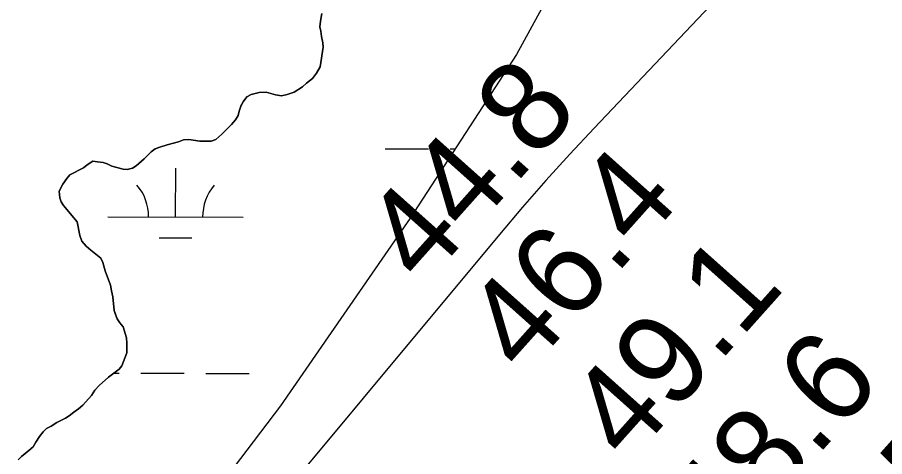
# Model space of a CAD drawing. Extents: x 3172297 to 3210190, y 958463 to 983887.
# Drawn here: x 3193154 to 3193795, y 965148 to 965472 of the extents above; entities that cross this region are included whole.
import ezdxf

# ---------------------------------------------------------------- set-up
doc = ezdxf.new("R2010")
doc.units = 0
for name, color, linetype in [('V-RIVR-RANG', 7, 'Continuous'), ('V-SITE-VEGE', 7, 'Continuous'), ('V-TOPO-MINR', 7, 'Continuous'), ('V-TOPO-SHOR', 7, 'Continuous'), ('V-WETL-SWMP', 7, 'Continuous')]:
    doc.layers.add(name, color=color, linetype=linetype)

msp = doc.modelspace()

# ---------------------------------------------------------------- linework, layer by layer
at = {"layer": 'V-SITE-VEGE'}
for p, q in [((3193379.05, 965474.97), (3193378.03, 965469.46)), ((3193378.03, 965469.46), (3193377.7, 965465.32)), ((3193377.7, 965465.32), (3193378.4, 965461.88)), ((3193378.4, 965461.88), (3193378.76, 965458.09)), ((3193378.76, 965458.09), (3193379.81, 965453.27)), ((3193380.16, 965450.18), (3193377.8, 965435.7)), ((3193379.81, 965453.27), (3193380.16, 965450.18)), ((3193377.8, 965435.7), (3193375.06, 965430.87)), ((3193375.06, 965430.87), (3193372.31, 965427.07)), ((3193367.85, 965423.61), (3193364.76, 965420.85)), ((3193372.31, 965427.07), (3193367.85, 965423.61)), ((3193332.74, 965416.61), (3193326.89, 965415.21)), ((3193337.9, 965416.97), (3193332.74, 965416.61)), ((3193344.8, 965414.93), (3193337.9, 965416.97)), ((3193358.57, 965417.04), (3193353.41, 965415.3)), ((3193364.76, 965420.85), (3193358.57, 965417.04)), ((3193321.05, 965409.69), (3193319.34, 965406.58)), ((3193323.79, 965413.48), (3193321.05, 965409.69)), ((3193326.89, 965415.21), (3193323.79, 965413.48)), ((3193349.28, 965414.25), (3193344.8, 965414.93)), ((3193353.41, 965415.3), (3193349.28, 965414.25)), ((3193319.34, 965406.58), (3193317.97, 965402.79)), ((3193315.24, 965396.58), (3193312.49, 965393.12)), ((3193317.29, 965399.68), (3193315.24, 965396.58)), ((3193317.97, 965402.79), (3193317.29, 965399.68)), ((3193312.49, 965393.12), (3193305.28, 965385.87)), ((3193305.28, 965385.87), (3193300.82, 965382.06)), ((3193265.01, 965378.16), (3193259.5, 965376.42)), ((3193273.27, 965380.25), (3193265.01, 965378.16)), ((3193277.05, 965381.64), (3193273.27, 965380.25)), ((3193280.84, 965382), (3193277.05, 965381.64)), ((3193289.11, 965380.65), (3193280.84, 965382)), ((3193297.38, 965380.67), (3193289.11, 965380.65)), ((3193300.82, 965382.06), (3193297.38, 965380.67)), ((3193252.97, 965372.95), (3193247.82, 965367.77)), ((3193256.06, 965375.03), (3193252.97, 965372.95)), ((3193259.5, 965376.42), (3193256.06, 965375.03)), ((3193209.94, 965365.92), (3193205.81, 965363.15)), ((3193213.38, 965365.59), (3193209.94, 965365.92)), ((3193217.52, 965364.91), (3193213.38, 965365.59)), ((3193220.62, 965363.89), (3193217.52, 965364.91)), ((3193247.82, 965367.77), (3193241.98, 965362.58)), ((3193203.06, 965361.08), (3193193.09, 965355.88)), ((3193205.81, 965363.15), (3193203.06, 965361.08)), ((3193224.07, 965362.18), (3193220.62, 965363.89)), ((3193232.34, 965360.14), (3193224.07, 965362.18)), ((3193235.45, 965359.81), (3193232.34, 965360.14)), ((3193239.23, 965360.85), (3193235.45, 965359.81)), ((3193241.98, 965362.58), (3193239.23, 965360.85)), ((3193190.69, 965353.11), (3193187.95, 965348.97)), ((3193193.09, 965355.88), (3193190.69, 965353.11)), ((3193187.95, 965348.97), (3193185.21, 965343.8)), ((3193185.21, 965343.8), (3193185.57, 965338.98)), ((3193185.57, 965338.98), (3193186.61, 965335.88)), ((3193186.61, 965335.88), (3193188.35, 965333.13)), ((3193188.35, 965333.13), (3193198.37, 965321.11)), ((3193198.37, 965321.11), (3193200.47, 965311.13)), ((3193200.47, 965311.13), (3193201.86, 965306.99)), ((3193201.86, 965306.99), (3193204.98, 965303.22)), ((3193204.98, 965303.22), (3193208.43, 965300.13)), ((3193208.43, 965300.13), (3193216.03, 965294.3)), ((3193216.03, 965294.3), (3193217.41, 965291.2)), ((3193217.41, 965291.2), (3193219.16, 965285.01)), ((3193219.16, 965285.01), (3193222.98, 965274.34)), ((3193222.98, 965274.34), (3193223.68, 965270.21)), ((3193223.68, 965270.21), (3193224.73, 965265.74)), ((3193224.73, 965265.74), (3193225.79, 965255.75)), ((3193225.79, 965255.75), (3193227.88, 965249.56)), ((3193227.88, 965249.56), (3193229.96, 965246.46)), ((3193229.96, 965246.46), (3193232.38, 965243.72)), ((3193232.38, 965243.72), (3193234.82, 965235.46)), ((3193234.82, 965235.46), (3193235.17, 965231.67)), ((3193235.17, 965231.67), (3193235.2, 965224.44)), ((3193235.2, 965224.44), (3193231.44, 965214.78)), ((3193229.38, 965212.36), (3193221.48, 965206.48)), ((3193231.44, 965214.78), (3193229.38, 965212.36)), ((3193221.48, 965206.48), (3193214.61, 965200.26)), ((3193214.61, 965200.26), (3193211.52, 965196.81)), ((3193209.12, 965193.01), (3193202.6, 965185.76)), ((3193211.52, 965196.81), (3193209.12, 965193.01)), ((3193202.6, 965185.76), (3193199.51, 965182.99)), ((3193196.08, 965180.57), (3193192.64, 965177.8)), ((3193199.51, 965182.99), (3193196.08, 965180.57)), ((3193183.35, 965172.95), (3193179.23, 965170.18)), ((3193189.89, 965176.07), (3193183.35, 965172.95)), ((3193192.64, 965177.8), (3193189.89, 965176.07)), ((3193173.39, 965166.03), (3193170.64, 965162.57)), ((3193175.79, 965168.45), (3193173.39, 965166.03)), ((3193179.23, 965170.18), (3193175.79, 965168.45)), ((3193170.64, 965162.57), (3193167.9, 965158.43)), ((3193165.85, 965154.98), (3193162.75, 965152.21)), ((3193167.9, 965158.43), (3193165.85, 965154.98)), ((3193162.75, 965152.21), (3193157.26, 965147.72))]:
    msp.add_line(p, q, dxfattribs=at)
at = {"layer": 'V-TOPO-MINR'}
msp.add_lwpolyline([(3194372.18, 966226.17), (3193580.04, 965390.46), (3193562.15, 965371.22), (3193544.51, 965351.76), (3193527.25, 965331.96), (3193510.25, 965311.93), (3193009.1, 964710.23), (3193002.17, 964701.92), (3192995.24, 964693.61), (3192988.3, 964685.31), (3192981.36, 964677.01), (3192969.12, 964662.37), (3192968.29, 964661.4), (3192967.46, 964660.43), (3192965.75, 964658.52), (3192960.13, 964652.39), (3192956.44, 964648.39), (3192952.71, 964644.43), (3192948.94, 964640.51), (3192945.15, 964636.61), (3192809.87, 964499.28), (3192738.63, 964426.54), (3192667.68, 964353.51), (3192597.16, 964280.07)], dxfattribs=at)
at = {"layer": 'V-TOPO-SHOR'}
msp.add_lwpolyline([(3193154.85, 965145.3), (3193157.26, 965147.72), (3193162.75, 965152.21), (3193165.85, 965154.98), (3193167.9, 965158.43), (3193170.64, 965162.57), (3193173.39, 965166.03), (3193175.79, 965168.45), (3193179.23, 965170.18), (3193183.35, 965172.95), (3193189.89, 965176.07), (3193192.64, 965177.8), (3193196.07, 965180.57), (3193199.51, 965182.99), (3193202.6, 965185.76), (3193209.12, 965193.01), (3193211.52, 965196.81), (3193214.61, 965200.26), (3193221.48, 965206.48), (3193229.38, 965212.36), (3193231.44, 965214.78), (3193235.2, 965224.44), (3193235.17, 965231.67), (3193234.82, 965235.46), (3193232.38, 965243.72), (3193229.96, 965246.46), (3193227.88, 965249.56), (3193226.84, 965252.66), (3193225.79, 965255.75), (3193224.73, 965265.74), (3193223.68, 965270.21), (3193222.98, 965274.34), (3193219.16, 965285.01), (3193217.41, 965291.2), (3193216.03, 965294.3), (3193208.43, 965300.13), (3193204.98, 965303.22), (3193201.86, 965307), (3193200.47, 965311.13), (3193198.37, 965321.11), (3193188.35, 965333.13), (3193186.61, 965335.88), (3193185.57, 965338.98), (3193185.21, 965343.8), (3193187.95, 965348.97), (3193190.69, 965353.11), (3193193.09, 965355.88), (3193203.06, 965361.08), (3193205.81, 965363.15), (3193209.94, 965365.92), (3193213.38, 965365.59), (3193217.52, 965364.91), (3193220.62, 965363.89), (3193224.07, 965362.18), (3193232.34, 965360.14), (3193235.45, 965359.81), (3193239.23, 965360.85), (3193241.98, 965362.58), (3193247.82, 965367.77), (3193252.97, 965372.95), (3193256.06, 965375.03), (3193259.5, 965376.42), (3193265.01, 965378.16), (3193273.27, 965380.25), (3193277.05, 965381.64), (3193280.84, 965382), (3193289.11, 965380.65), (3193297.38, 965380.67), (3193300.82, 965382.06), (3193305.28, 965385.87), (3193312.49, 965393.12), (3193315.24, 965396.58), (3193317.29, 965399.68), (3193317.97, 965402.79), (3193319.34, 965406.58), (3193321.05, 965409.69), (3193323.79, 965413.48), (3193326.89, 965415.21), (3193332.74, 965416.61), (3193337.9, 965416.97), (3193344.8, 965414.93), (3193349.28, 965414.25), (3193353.41, 965415.3), (3193358.57, 965417.04), (3193364.76, 965420.85), (3193367.85, 965423.61), (3193372.31, 965427.07), (3193375.06, 965430.87), (3193377.8, 965435.7), (3193380.16, 965450.18), (3193379.81, 965453.27), (3193378.76, 965458.09), (3193378.4, 965461.88), (3193377.7, 965465.32), (3193378.03, 965469.46), (3193379.05, 965474.97)], dxfattribs=at)
at = {"layer": 'V-WETL-SWMP'}
for p, q in [((3193425.81, 965375.1), (3193457.81, 965375.02)), ((3193473.81, 965374.98), (3193477.46, 965374.97)), ((3193271.09, 965324.74), (3193271.18, 965360.74)), ((3193221.09, 965324.86), (3193321.09, 965324.62)), ((3193259.05, 965309.34), (3193283.05, 965309.28)), ((3193225.42, 965209.42), (3193229.4, 965209.41)), ((3193245.4, 965209.37), (3193277.4, 965209.29)), ((3193293.4, 965209.25), (3193325.4, 965209.17))]:
    msp.add_line(p, q, dxfattribs=at)
for points in [[(3193738.09, 965817.65), (3193624.49, 965630.72), (3193522.75, 965444.79), (3193444.26, 965323.8), (3193348.56, 965185.35), (3193249.16, 965054.18), (3193135.29, 964906.47), (3193014.29, 964734.08), (3193007.95, 964728.57), (3192766.54, 964428.5), (3192623.52, 964274.2)], [(3193154.85, 965145.3), (3193157.26, 965147.72), (3193162.75, 965152.21), (3193165.85, 965154.98), (3193167.9, 965158.43), (3193170.64, 965162.57), (3193173.39, 965166.03), (3193175.79, 965168.45), (3193179.23, 965170.18), (3193183.35, 965172.95), (3193189.89, 965176.07), (3193192.64, 965177.8), (3193196.07, 965180.57), (3193199.51, 965182.99), (3193202.6, 965185.76), (3193209.12, 965193.01), (3193211.52, 965196.81), (3193214.61, 965200.26), (3193221.48, 965206.48), (3193229.38, 965212.36), (3193231.44, 965214.78), (3193235.2, 965224.44), (3193235.17, 965231.67), (3193234.82, 965235.46), (3193232.38, 965243.72), (3193229.96, 965246.47), (3193227.88, 965249.56), (3193226.84, 965252.66), (3193225.79, 965255.75), (3193224.73, 965265.74), (3193223.68, 965270.21), (3193222.98, 965274.34), (3193219.16, 965285.01), (3193217.41, 965291.2), (3193216.02, 965294.3), (3193208.43, 965300.13), (3193204.97, 965303.22), (3193201.86, 965307), (3193200.47, 965311.13), (3193198.37, 965321.11), (3193188.34, 965333.13), (3193186.61, 965335.88), (3193185.57, 965338.98), (3193185.21, 965343.8), (3193187.95, 965348.97), (3193190.69, 965353.12), (3193193.09, 965355.88), (3193203.06, 965361.08), (3193205.81, 965363.15), (3193209.94, 965365.92), (3193213.38, 965365.59), (3193217.52, 965364.91), (3193220.62, 965363.89), (3193224.07, 965362.18), (3193232.35, 965360.14), (3193235.45, 965359.81), (3193239.23, 965360.85), (3193241.98, 965362.58), (3193247.82, 965367.77), (3193252.97, 965372.95), (3193256.06, 965375.03), (3193259.5, 965376.42), (3193265.01, 965378.16), (3193273.27, 965380.25), (3193277.05, 965381.64), (3193280.84, 965382), (3193289.11, 965380.65), (3193297.38, 965380.67), (3193300.82, 965382.06), (3193305.28, 965385.87), (3193312.49, 965393.12), (3193315.24, 965396.58), (3193317.29, 965399.68), (3193317.97, 965402.79), (3193319.34, 965406.58), (3193321.05, 965409.68), (3193323.79, 965413.48), (3193326.89, 965415.21), (3193332.74, 965416.61), (3193337.9, 965416.97), (3193344.8, 965414.93), (3193349.28, 965414.25), (3193353.41, 965415.3), (3193358.57, 965417.04), (3193364.76, 965420.85), (3193367.85, 965423.61), (3193372.31, 965427.07), (3193375.06, 965430.87), (3193377.8, 965435.7), (3193380.16, 965450.18), (3193379.81, 965453.28), (3193378.76, 965458.09), (3193378.4, 965461.88), (3193377.7, 965465.32), (3193378.03, 965469.46), (3193379.05, 965474.97)]]:
    msp.add_lwpolyline(points, dxfattribs=at)
for centre, start, end in [((3193215.85, 965325.35), 359.0865, 40.63016), ((3193326.34, 965325.08), 139.0865, 180.63016)]:
    msp.add_arc(centre, 35.25, start, end, dxfattribs=at)

# ---------------------------------------------------------------- texts
at = {"layer": 'V-RIVR-RANG'}
for s, p in [('44.8', (3193454.36, 965272.96)), ('46.4', (3193529.13, 965206.56)), ('49.1', (3193605.48, 965141.93)), ('48.6', (3193677.44, 965072.38)), ('46.5', (3193753.45, 965007.35))]:
    msp.add_text(s, height=67, rotation=48.24833, dxfattribs=at).set_placement(p)

doc.saveas('drawing.dxf')
